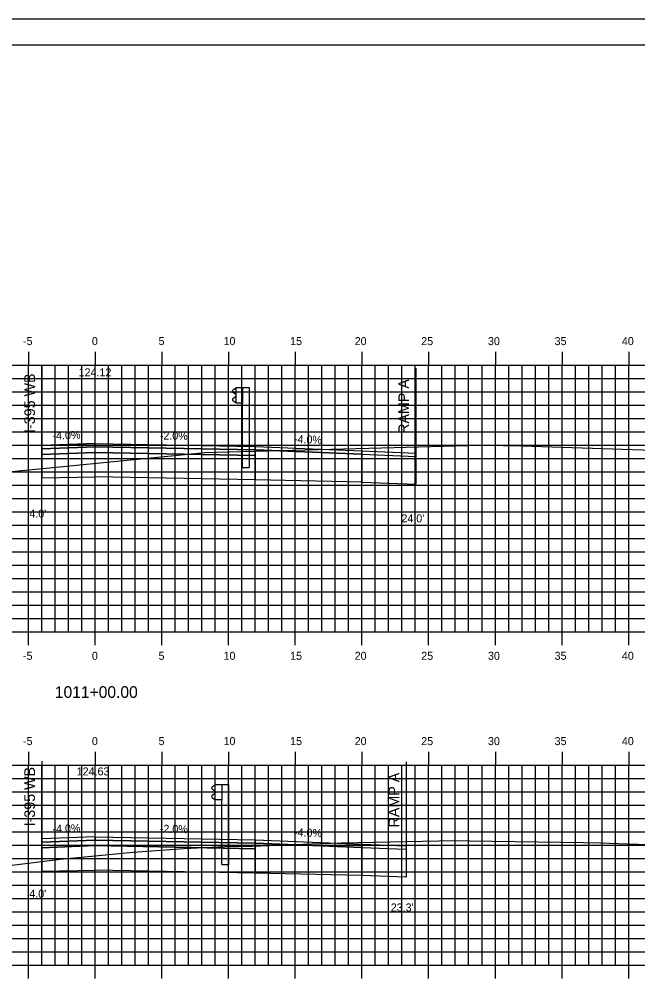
# Model space of a CAD drawing. Extents: x 852182 to 852354, y 365624 to 365734.
# Drawn here: x 852259.3 to 852305.7, y 365661.8 to 365734 of the extents above; entities that cross this region are included whole.
import ezdxf

# ---------------------------------------------------------------- set-up
doc = ezdxf.new("R2010")
doc.units = 0
for name, color, linetype in [('ANNOTATION', 7, 'Continuous'), ('BORDER', 7, 'Continuous'), ('D_Roadway_Centerline', 7, 'Continuous'), ('D_Roadway_Centerline_Text', 7, 'Continuous'), ('D_Roadway_Edge_Shoulder', 7, 'Continuous'), ('D_Roadway_Edge_TW', 7, 'Continuous'), ('D_Roadway_FinishedGrade', 7, 'Continuous'), ('D_Roadway_Pavement', 7, 'Continuous'), ('D_Roadway_SubGrade', 7, 'Continuous'), ('D_Text_Standard', 7, 'Continuous'), ('H_V ANNOTATION', 7, 'Continuous'), ('M_Guardrail', 7, 'Continuous'), ('M_Roadway_Centerline', 7, 'Continuous'), ('MAJOR', 7, 'Continuous'), ('MINOR', 7, 'Continuous'), ('PLOT BOUNDARY', 7, 'Continuous'), ('S_Roadway_Centerline', 7, 'Continuous')]:
    doc.layers.add(name, color=color, linetype=linetype)

msp = doc.modelspace()

# ---------------------------------------------------------------- linework, layer by layer
at = {"layer": 'BORDER'}
msp.add_lwpolyline([(852190.035, 365627.027), (852350.035, 365627.027), (852350.035, 365732.027), (852190.035, 365732.027)], close=True, dxfattribs=at)
at = {"layer": 'D_Roadway_Centerline'}
for p, q in [((852285.035, 365701.592), (852289.073, 365701.43)), ((852285.035, 365701.342), (852289.073, 365701.18)), ((852285.035, 365672.099), (852288.338, 365671.967)), ((852285.035, 365671.849), (852288.338, 365671.717)), ((852288.338, 365671.777), (852288.338, 365669.613))]:
    msp.add_line(p, q, dxfattribs=at)
for points in [[(852261.035, 365701.992), (852261.035, 365701.992), (852261.036, 365701.992), (852265.035, 365702.152), (852265.037, 365702.152), (852277.035, 365701.912), (852285.035, 365701.592)], [(852288.338, 365669.613), (852285.035, 365669.759)]]:
    msp.add_lwpolyline(points, dxfattribs=at)
at = {"layer": 'D_Roadway_Edge_Shoulder'}
for points in [[(852265.035, 365702.152), (852261.035, 365701.992), (852261.036, 365701.742), (852265.035, 365701.902)], [(852277.035, 365701.912), (852285.035, 365701.592), (852285.035, 365701.342), (852277.035, 365701.662)], [(852265.035, 365672.659), (852261.035, 365672.499), (852261.035, 365672.249), (852265.035, 365672.409)], [(852277.035, 365672.419), (852285.035, 365672.099), (852285.035, 365671.849), (852277.035, 365672.169)]]:
    msp.add_lwpolyline(points, close=True, dxfattribs=at)
at = {"layer": 'D_Roadway_Edge_TW'}
for points in [[(852265.035, 365702.152), (852277.035, 365701.912), (852277.035, 365701.662), (852265.035, 365701.902)], [(852265.035, 365672.659), (852277.035, 365672.419), (852277.035, 365672.169), (852265.035, 365672.409)]]:
    msp.add_lwpolyline(points, close=True, dxfattribs=at)
for points in [[(852277.035, 365701.912), (852277.035, 365701.745)], [(852277.035, 365672.419), (852277.035, 365672.253)]]:
    msp.add_lwpolyline(points, dxfattribs=at)
at = {"layer": 'D_Roadway_FinishedGrade'}
for p, q in [((852265.035, 365702.152), (852265.035, 365701.902)), ((852261.036, 365701.992), (852261.036, 365701.742)), ((852277.035, 365701.912), (852277.035, 365701.662)), ((852285.035, 365701.592), (852285.035, 365701.342)), ((852261.035, 365672.499), (852261.035, 365672.249)), ((852265.035, 365672.659), (852265.035, 365672.409)), ((852277.035, 365672.419), (852277.035, 365672.169)), ((852285.035, 365672.099), (852285.035, 365671.849))]:
    msp.add_line(p, q, dxfattribs=at)
msp.add_lwpolyline([(852285.035, 365699.252), (852289.072, 365699.101), (852289.073, 365701.292)], dxfattribs=at)
at = {"layer": 'D_Roadway_Pavement'}
for points in [[(852265.035, 365701.902), (852261.036, 365701.742), (852261.035, 365701.325), (852265.035, 365701.485)], [(852265.035, 365701.902), (852277.035, 365701.662), (852277.035, 365701.245), (852265.035, 365701.485)], [(852265.035, 365672.409), (852261.035, 365672.249), (852261.035, 365671.833), (852265.035, 365671.993)], [(852265.035, 365672.409), (852277.035, 365672.169), (852277.035, 365671.753), (852265.035, 365671.993)]]:
    msp.add_lwpolyline(points, close=True, dxfattribs=at)
for points in [[(852277.035, 365701.745), (852277.035, 365701.245)], [(852277.035, 365701.745), (852277.035, 365701.245)], [(852277.035, 365672.253), (852277.035, 365671.753)], [(852277.035, 365672.253), (852277.035, 365671.753)]]:
    msp.add_lwpolyline(points, dxfattribs=at)
at = {"layer": 'D_Roadway_SubGrade'}
for p, q in [((852261.036, 365707.914), (852261.036, 365699.572)), ((852289.073, 365707.789), (852289.073, 365699.101)), ((852261.035, 365678.315), (852261.035, 365670.079)), ((852288.338, 365678.272), (852288.338, 365669.613))]:
    msp.add_line(p, q, dxfattribs=at)
for points in [[(852265.035, 365701.485), (852261.035, 365701.325), (852261.035, 365701.825), (852261.035, 365701.992), (852261.035, 365699.572), (852265.035, 365699.652)], [(852265.035, 365701.485), (852277.035, 365701.245), (852277.035, 365699.412), (852265.035, 365699.652)], [(852277.035, 365701.245), (852277.035, 365701.662), (852285.035, 365701.342), (852285.035, 365701.592), (852285.035, 365699.252), (852277.035, 365699.412)], [(852265.035, 365671.993), (852261.035, 365671.833), (852261.035, 365672.333), (852261.035, 365672.499), (852261.035, 365670.079), (852265.035, 365670.159)], [(852265.035, 365671.993), (852277.035, 365671.753), (852277.035, 365669.919), (852265.035, 365670.159)], [(852277.035, 365671.753), (852277.035, 365672.169), (852285.035, 365671.849), (852285.035, 365672.099), (852285.035, 365669.759), (852277.035, 365669.919)]]:
    msp.add_lwpolyline(points, close=True, dxfattribs=at)
for points in [[(852277.035, 365701.245), (852277.035, 365699.412)], [(852277.035, 365671.753), (852277.035, 365669.919)]]:
    msp.add_lwpolyline(points, dxfattribs=at)
at = {"layer": 'M_Guardrail'}
for p, q in [((852275.504, 365706.243), (852275.36, 365706.143)), ((852275.36, 365706), (852275.555, 365705.864)), ((852275.555, 365705.644), (852275.36, 365705.508)), ((852275.602, 365706.264), (852275.52, 365706.25)), ((852275.589, 365705.799), (852275.589, 365705.708)), ((852275.602, 365706.337), (852276.092, 365706.337)), ((852275.602, 365705.17), (852275.602, 365706.337)), ((852276.092, 365706.337), (852276.584, 365706.337)), ((852276.092, 365706.337), (852276.092, 365705.17)), ((852276.584, 365706.337), (852276.584, 365700.337)), ((852275.36, 365705.364), (852275.504, 365705.264)), ((852275.52, 365705.258), (852275.602, 365705.243)), ((852276.092, 365705.17), (852275.602, 365705.17)), ((852276.092, 365700.337), (852276.092, 365705.17)), ((852276.092, 365700.337), (852276.584, 365700.337)), ((852273.943, 365676.485), (852273.799, 365676.385)), ((852273.799, 365676.242), (852273.995, 365676.105)), ((852274.042, 365676.506), (852273.96, 365676.492)), ((852274.028, 365676.041), (852274.028, 365675.95)), ((852274.042, 365676.579), (852274.531, 365676.579)), ((852274.042, 365675.412), (852274.042, 365676.579)), ((852274.531, 365676.579), (852275.023, 365676.579)), ((852274.531, 365676.579), (852274.531, 365675.412)), ((852275.023, 365676.579), (852275.023, 365670.579)), ((852273.995, 365675.886), (852273.799, 365675.749)), ((852273.799, 365675.606), (852273.943, 365675.506)), ((852273.96, 365675.5), (852274.042, 365675.485)), ((852274.531, 365675.412), (852274.042, 365675.412)), ((852274.531, 365670.579), (852274.531, 365675.412)), ((852274.531, 365670.579), (852275.023, 365670.579))]:
    msp.add_line(p, q, dxfattribs=at)
for centre, major_axis, start_param, end_param in [((852275.41, 365706.071), (-0.0877, 0), 5.323254, 7.243116), ((852275.527, 365706.209), (-0.0417, 0), 4.886922, 5.323254), ((852275.51, 365705.799), (0.0789, 0), 0, 0.959931), ((852275.51, 365705.708), (0.0789, 0), 5.323254, 6.283185), ((852275.41, 365705.436), (-0.0877, 0), 5.323254, 7.243116), ((852275.527, 365705.298), (-0.0417, 0), 0.959931, 1.396263), ((852273.85, 365676.313), (-0.0877, 0), 5.323254, 7.243116), ((852273.967, 365676.451), (-0.0417, 0), 4.886922, 5.323254), ((852273.95, 365676.041), (0.0789, 0), 0, 0.959931), ((852273.85, 365675.678), (-0.0877, 0), 5.323254, 7.243116), ((852273.967, 365675.54), (-0.0417, 0), 0.959931, 1.396263), ((852273.95, 365675.95), (0.0789, 0), 5.323254, 6.283185)]:
    msp.add_ellipse(centre, major_axis=major_axis, ratio=0.995501, start_param=start_param, end_param=end_param, dxfattribs=at)
at = {"layer": 'MAJOR'}
for p, q in [((852260.035, 365709.029), (852260.035, 365708.027)), ((852265.035, 365709.029), (852265.035, 365708.027)), ((852270.035, 365709.029), (852270.035, 365708.027)), ((852275.035, 365709.029), (852275.035, 365708.027)), ((852280.035, 365709.029), (852280.035, 365708.027)), ((852285.035, 365709.029), (852285.035, 365708.027)), ((852290.035, 365709.029), (852290.035, 365708.027)), ((852295.035, 365709.029), (852295.035, 365708.027)), ((852300.035, 365709.029), (852300.035, 365708.027)), ((852305.035, 365709.029), (852305.035, 365708.027)), ((852195.035, 365708.027), (852335.035, 365708.027)), ((852195.035, 365708.027), (852335.035, 365708.027)), ((852260.035, 365688.027), (852260.035, 365708.027)), ((852265.035, 365688.027), (852265.035, 365708.027)), ((852270.035, 365688.027), (852270.035, 365708.027)), ((852275.035, 365688.027), (852275.035, 365708.027)), ((852280.035, 365688.027), (852280.035, 365708.027)), ((852285.035, 365688.027), (852285.035, 365708.027)), ((852290.035, 365688.027), (852290.035, 365708.027)), ((852295.035, 365688.027), (852295.035, 365708.027)), ((852300.035, 365688.027), (852300.035, 365708.027)), ((852305.035, 365688.027), (852305.035, 365708.027)), ((852195.035, 365703.027), (852335.035, 365703.027)), ((852195.035, 365698.027), (852335.035, 365698.027)), ((852195.035, 365693.027), (852335.035, 365693.027)), ((852195.035, 365688.027), (852335.035, 365688.027)), ((852195.035, 365688.027), (852335.035, 365688.027)), ((852260.035, 365687.025), (852260.035, 365688.027)), ((852265.035, 365687.025), (852265.035, 365688.027)), ((852270.035, 365687.025), (852270.035, 365688.027)), ((852275.035, 365687.025), (852275.035, 365688.027)), ((852280.035, 365687.025), (852280.035, 365688.027)), ((852285.035, 365687.025), (852285.035, 365688.027)), ((852290.035, 365687.025), (852290.035, 365688.027)), ((852295.035, 365687.025), (852295.035, 365688.027)), ((852300.035, 365687.025), (852300.035, 365688.027)), ((852305.035, 365687.025), (852305.035, 365688.027)), ((852260.035, 365679.029), (852260.035, 365678.027)), ((852265.035, 365679.029), (852265.035, 365678.027)), ((852270.035, 365679.029), (852270.035, 365678.027)), ((852275.035, 365679.029), (852275.035, 365678.027)), ((852280.035, 365679.029), (852280.035, 365678.027)), ((852285.035, 365679.029), (852285.035, 365678.027)), ((852290.035, 365679.029), (852290.035, 365678.027)), ((852295.035, 365679.029), (852295.035, 365678.027)), ((852300.035, 365679.029), (852300.035, 365678.027)), ((852305.035, 365679.029), (852305.035, 365678.027)), ((852195.035, 365678.027), (852335.035, 365678.027)), ((852195.035, 365678.027), (852335.035, 365678.027)), ((852260.035, 365663.027), (852260.035, 365678.027)), ((852265.035, 365663.027), (852265.035, 365678.027)), ((852270.035, 365663.027), (852270.035, 365678.027)), ((852275.035, 365663.027), (852275.035, 365678.027)), ((852280.035, 365663.027), (852280.035, 365678.027)), ((852285.035, 365663.027), (852285.035, 365678.027)), ((852290.035, 365663.027), (852290.035, 365678.027)), ((852295.035, 365663.027), (852295.035, 365678.027)), ((852300.035, 365663.027), (852300.035, 365678.027)), ((852305.035, 365663.027), (852305.035, 365678.027)), ((852195.035, 365673.027), (852335.035, 365673.027)), ((852195.035, 365668.027), (852335.035, 365668.027)), ((852195.035, 365663.027), (852335.035, 365663.027)), ((852195.035, 365663.027), (852335.035, 365663.027)), ((852260.035, 365662.025), (852260.035, 365663.027)), ((852265.035, 365662.025), (852265.035, 365663.027)), ((852270.035, 365662.025), (852270.035, 365663.027)), ((852275.035, 365662.025), (852275.035, 365663.027)), ((852280.035, 365662.025), (852280.035, 365663.027)), ((852285.035, 365662.025), (852285.035, 365663.027)), ((852290.035, 365662.025), (852290.035, 365663.027)), ((852295.035, 365662.025), (852295.035, 365663.027)), ((852300.035, 365662.025), (852300.035, 365663.027)), ((852305.035, 365662.025), (852305.035, 365663.027))]:
    msp.add_line(p, q, dxfattribs=at)
at = {"layer": 'MINOR'}
for p, q in [((852261.035, 365688.027), (852261.035, 365708.027)), ((852262.035, 365688.027), (852262.035, 365708.027)), ((852263.035, 365688.027), (852263.035, 365708.027)), ((852264.035, 365688.027), (852264.035, 365708.027)), ((852266.035, 365688.027), (852266.035, 365708.027)), ((852267.035, 365688.027), (852267.035, 365708.027)), ((852268.035, 365688.027), (852268.035, 365708.027)), ((852269.035, 365688.027), (852269.035, 365708.027)), ((852271.035, 365688.027), (852271.035, 365708.027)), ((852272.035, 365688.027), (852272.035, 365708.027)), ((852273.035, 365688.027), (852273.035, 365708.027)), ((852274.035, 365688.027), (852274.035, 365708.027)), ((852276.035, 365688.027), (852276.035, 365708.027)), ((852277.035, 365688.027), (852277.035, 365708.027)), ((852278.035, 365688.027), (852278.035, 365708.027)), ((852279.035, 365688.027), (852279.035, 365708.027)), ((852281.035, 365688.027), (852281.035, 365708.027)), ((852282.035, 365688.027), (852282.035, 365708.027)), ((852283.035, 365688.027), (852283.035, 365708.027)), ((852284.035, 365688.027), (852284.035, 365708.027)), ((852286.035, 365688.027), (852286.035, 365708.027)), ((852287.035, 365688.027), (852287.035, 365708.027)), ((852288.035, 365688.027), (852288.035, 365708.027)), ((852289.035, 365688.027), (852289.035, 365708.027)), ((852291.035, 365688.027), (852291.035, 365708.027)), ((852292.035, 365688.027), (852292.035, 365708.027)), ((852293.035, 365688.027), (852293.035, 365708.027)), ((852294.035, 365688.027), (852294.035, 365708.027)), ((852296.035, 365688.027), (852296.035, 365708.027)), ((852297.035, 365688.027), (852297.035, 365708.027)), ((852298.035, 365688.027), (852298.035, 365708.027)), ((852299.035, 365688.027), (852299.035, 365708.027)), ((852301.035, 365688.027), (852301.035, 365708.027)), ((852302.035, 365688.027), (852302.035, 365708.027)), ((852303.035, 365688.027), (852303.035, 365708.027)), ((852304.035, 365688.027), (852304.035, 365708.027)), ((852195.035, 365707.027), (852335.035, 365707.027)), ((852195.035, 365706.027), (852335.035, 365706.027)), ((852195.035, 365705.027), (852335.035, 365705.027)), ((852195.035, 365704.027), (852335.035, 365704.027)), ((852195.035, 365702.027), (852335.035, 365702.027)), ((852195.035, 365701.027), (852335.035, 365701.027)), ((852195.035, 365700.027), (852335.035, 365700.027)), ((852195.035, 365699.027), (852335.035, 365699.027)), ((852195.035, 365697.027), (852335.035, 365697.027)), ((852195.035, 365696.027), (852335.035, 365696.027)), ((852195.035, 365695.027), (852335.035, 365695.027)), ((852195.035, 365694.027), (852335.035, 365694.027)), ((852195.035, 365692.027), (852335.035, 365692.027)), ((852195.035, 365691.027), (852335.035, 365691.027)), ((852195.035, 365690.027), (852335.035, 365690.027)), ((852195.035, 365689.027), (852335.035, 365689.027)), ((852261.035, 365663.027), (852261.035, 365678.027)), ((852262.035, 365663.027), (852262.035, 365678.027)), ((852263.035, 365663.027), (852263.035, 365678.027)), ((852264.035, 365663.027), (852264.035, 365678.027)), ((852266.035, 365663.027), (852266.035, 365678.027)), ((852267.035, 365663.027), (852267.035, 365678.027)), ((852268.035, 365663.027), (852268.035, 365678.027)), ((852269.035, 365663.027), (852269.035, 365678.027)), ((852271.035, 365663.027), (852271.035, 365678.027)), ((852272.035, 365663.027), (852272.035, 365678.027)), ((852273.035, 365663.027), (852273.035, 365678.027)), ((852274.035, 365663.027), (852274.035, 365678.027)), ((852276.035, 365663.027), (852276.035, 365678.027)), ((852277.035, 365663.027), (852277.035, 365678.027)), ((852278.035, 365663.027), (852278.035, 365678.027)), ((852279.035, 365663.027), (852279.035, 365678.027)), ((852281.035, 365663.027), (852281.035, 365678.027)), ((852282.035, 365663.027), (852282.035, 365678.027)), ((852283.035, 365663.027), (852283.035, 365678.027)), ((852284.035, 365663.027), (852284.035, 365678.027)), ((852286.035, 365663.027), (852286.035, 365678.027)), ((852287.035, 365663.027), (852287.035, 365678.027)), ((852288.035, 365663.027), (852288.035, 365678.027)), ((852289.035, 365663.027), (852289.035, 365678.027)), ((852291.035, 365663.027), (852291.035, 365678.027)), ((852292.035, 365663.027), (852292.035, 365678.027)), ((852293.035, 365663.027), (852293.035, 365678.027)), ((852294.035, 365663.027), (852294.035, 365678.027)), ((852296.035, 365663.027), (852296.035, 365678.027)), ((852297.035, 365663.027), (852297.035, 365678.027)), ((852298.035, 365663.027), (852298.035, 365678.027)), ((852299.035, 365663.027), (852299.035, 365678.027)), ((852301.035, 365663.027), (852301.035, 365678.027)), ((852302.035, 365663.027), (852302.035, 365678.027)), ((852303.035, 365663.027), (852303.035, 365678.027)), ((852304.035, 365663.027), (852304.035, 365678.027)), ((852195.035, 365677.027), (852335.035, 365677.027)), ((852195.035, 365676.027), (852335.035, 365676.027)), ((852195.035, 365675.027), (852335.035, 365675.027)), ((852195.035, 365674.027), (852335.035, 365674.027)), ((852195.035, 365672.027), (852335.035, 365672.027)), ((852195.035, 365671.027), (852335.035, 365671.027)), ((852195.035, 365670.027), (852335.035, 365670.027)), ((852195.035, 365669.027), (852335.035, 365669.027)), ((852195.035, 365667.027), (852335.035, 365667.027)), ((852195.035, 365666.027), (852335.035, 365666.027)), ((852195.035, 365665.027), (852335.035, 365665.027)), ((852195.035, 365664.027), (852335.035, 365664.027))]:
    msp.add_line(p, q, dxfattribs=at)
at = {"layer": 'PLOT BOUNDARY'}
msp.add_lwpolyline([(852181.942, 365623.968), (852351.942, 365623.968), (852351.942, 365733.968), (852181.942, 365733.968)], close=True, dxfattribs=at)
at = {"layer": 'S_Roadway_Centerline'}
for points in [[(852256.687, 365699.838), (852261.621, 365700.327), (852273.269, 365701.47), (852274.137, 365701.506), (852287.45, 365701.841), (852292.981, 365701.992), (852293.529, 365702.032), (852294.212, 365702.018), (852297.012, 365701.969), (852314.385, 365701.407), (852316.37, 365701.301), (852318.61, 365701.183), (852324.48, 365700.337), (852334.948, 365698.342), (852335.035, 365698.321)], [(852254.618, 365670.011), (852262.427, 365670.97), (852267.878, 365671.488), (852271.682, 365671.768), (852274.775, 365671.918), (852276.815, 365671.956), (852281.912, 365672.15), (852283.501, 365672.194), (852290.788, 365672.344), (852292.581, 365672.368), (852293.095, 365672.356), (852301.638, 365672.231), (852302.92, 365672.209), (852304.916, 365672.121), (852314.905, 365671.829), (852318.092, 365671.724), (852318.539, 365671.667), (852327.398, 365670.308), (852335.035, 365668.663)]]:
    msp.add_lwpolyline(points, dxfattribs=at)

# ---------------------------------------------------------------- texts
at = {"layer": 'ANNOTATION'}
for s, height, rotation, p in [('I-395 WB', 0.8, 90, (852260.529, 365702.941)), ('RAMP A', 0.8, 90, (852288.566, 365702.873)), ('-4.0%', 0.6, 2.2904, (852261.852, 365702.425)), ('-2.0%', 0.6, 358.85423, (852269.879, 365702.455)), ('-4.0%', 0.6, 357.70931, (852279.931, 365702.197)), ('I-395 WB', 0.8, 90, (852260.528, 365673.432)), ('RAMP A', 0.8, 90, (852287.831, 365673.356)), ('-4.0%', 0.6, 2.29049, (852261.851, 365672.932)), ('-2.0%', 0.6, 358.85422, (852269.881, 365672.962)), ('-4.0%', 0.6, 357.70929, (852279.933, 365672.704))]:
    msp.add_text(s, height=height, rotation=rotation, dxfattribs=at).set_placement(p)
at = {"layer": 'D_Roadway_Centerline'}
for s, p in [('C', (852265.03, 365702.152)), ('L', (852265.035, 365702.144)), ('C', (852265.03, 365672.659)), ('L', (852265.035, 365672.652))]:
    msp.add_text(s, height=0.0146, dxfattribs=at).set_placement(p)
at = {"layer": 'D_Roadway_Centerline_Text'}
for s, p in [('124.12', (852263.797, 365707.184)), ('124.63', (852263.652, 365677.255))]:
    msp.add_text(s, height=0.6, dxfattribs=at).set_placement(p)
at = {"layer": 'D_Text_Standard'}
for s, p in [("4.0'", (852260.103, 365696.593)), ("24.0'", (852287.995, 365696.235)), ("4.0'", (852260.102, 365668.083)), ("23.3'", (852287.196, 365667.052))]:
    msp.add_text(s, height=0.6, dxfattribs=at).set_placement(p)
at = {"layer": 'H_V ANNOTATION'}
for s, height, p in [('-5', 0.6, (852259.626, 365709.527)), ('0', 0.6, (852264.794, 365709.527)), ('5', 0.6, (852269.786, 365709.527)), ('10', 0.6, (852274.661, 365709.527)), ('15', 0.6, (852279.653, 365709.527)), ('20', 0.6, (852284.489, 365709.527)), ('25', 0.6, (852289.481, 365709.527)), ('30', 0.6, (852294.484, 365709.527)), ('35', 0.6, (852299.476, 365709.527)), ('40', 0.6, (852304.521, 365709.527)), ('-5', 0.6, (852259.626, 365685.927)), ('0', 0.6, (852264.794, 365685.927)), ('5', 0.6, (852269.786, 365685.927)), ('10', 0.6, (852274.661, 365685.927)), ('15', 0.6, (852279.653, 365685.927)), ('20', 0.6, (852284.489, 365685.927)), ('25', 0.6, (852289.481, 365685.927)), ('30', 0.6, (852294.484, 365685.927)), ('35', 0.6, (852299.476, 365685.927)), ('40', 0.6, (852304.521, 365685.927)), ('1011+00.00', 0.875, (852262.016, 365683.07)), ('-5', 0.6, (852259.626, 365679.527)), ('0', 0.6, (852264.794, 365679.527)), ('5', 0.6, (852269.786, 365679.527)), ('10', 0.6, (852274.661, 365679.527)), ('15', 0.6, (852279.653, 365679.527)), ('20', 0.6, (852284.489, 365679.527)), ('25', 0.6, (852289.481, 365679.527)), ('30', 0.6, (852294.484, 365679.527)), ('35', 0.6, (852299.476, 365679.527)), ('40', 0.6, (852304.521, 365679.527))]:
    msp.add_text(s, height=height, dxfattribs=at).set_placement(p)
at = {"layer": 'M_Roadway_Centerline'}
for s, p in [('C', (852293.524, 365702.032)), ('L', (852293.529, 365702.025)), ('C', (852292.575, 365672.368)), ('L', (852292.581, 365672.36))]:
    msp.add_text(s, height=0.0146, dxfattribs=at).set_placement(p)

doc.saveas('drawing.dxf')
